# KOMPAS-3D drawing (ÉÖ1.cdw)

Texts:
  Casper
  Текст на чертеже
  Размерные надписи
  Шероховатость
  Линия-выноска #1
  Линия-выноска #2
  Линия-выноска #3
  Отклонения формы и база
  Заголовок таблицы
  Ячейка таблицы
  Стрелка вида
  Обозначение изменения
  Фигурная скобка
  Номер узла
  Марка координационной оси
  VRCB
  Выносная надпись
  Обозначение узла
  Марка/позиционное обозначение с линией-выноской
  Марка/позиционное обозначение на линии
  Марка/позиционное обозначение без линии-выноски
  Номер группы
  Р кВт
  Ток, А
  Гр1
  Гр2
  Гр3
  Гр4
  ВА 88-32 (3)
  ВА 47-29 (3)
  ДГУ
  ВРУ (ЩМП-3)
  Рр=55.0 кВт
  Гр5
  Гр6
  Гр7
  Щиток ЩО1
  Щиток ЩО2
  Щиток ЩО3
  Щиток ЩР1
  Щиток ЩР2
  Щиток ЩР3
  ВР 32-35 250А
  ВА 47-100(3)
  ВА 47-29 ()
  ВА 47-29 (1)
  ЩАО 1
  ЩАО 2
  ЩАО 3
  ЩАО 4
  ЩГП (ЩРН-12)
  ВВГнгLS 5х16 мм2 скрыто
  в гофр. ПВХ трубе
  ВВГнгLS 5х50 мм2
  ВВГнгLS 5х25 мм2 скрыто
  CONTINUOUS0
Dimensions and other numbers on the sheet: 7; 13.22; 20.2; 5.0; 7.9; 100А; 40А; 20А; 25А; 16А; 4; 1:1; 1; 0; 2; 3; 5; 6; 8; 9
